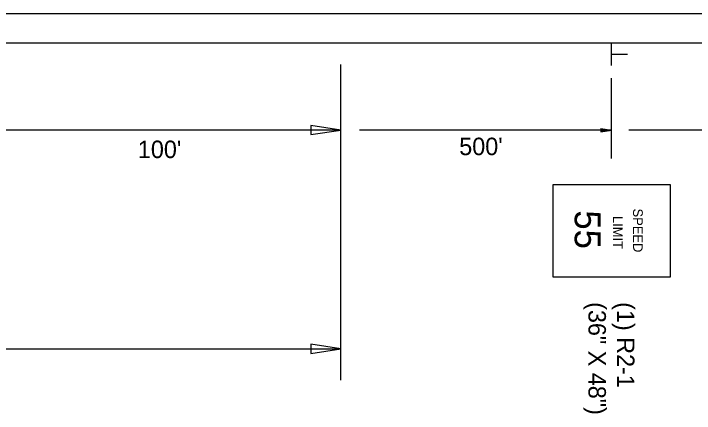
# Model space of a CAD drawing. Extents: x 1678017 to 1687792, y 404433 to 413488.
# Drawn here: x 1678979.75 to 1679003.11, y 409241.21 to 409254.94 of the extents above; entities that cross this region are included whole.
import ezdxf

# ---------------------------------------------------------------- set-up
doc = ezdxf.new("R2010")
doc.units = 0
doc.layers.add('Default', color=7, linetype='Continuous')

msp = doc.modelspace()

# ---------------------------------------------------------------- linework, layer by layer
at = {"layer": 'Default'}
for p, q in [((1678966.108, 409254.939), (1678990.693, 409254.939)), ((1678990.693, 409254.939), (1678997.456, 409254.939)), ((1678997.456, 409254.939), (1679009.188, 409254.939)), ((1678953.639, 409253.939), (1679044.491, 409253.939)), ((1679000.269, 409253.157), (1679000.269, 409253.939)), ((1679000.281, 409253.546), (1679000.815, 409253.546)), ((1678990.975, 409242.349), (1678990.975, 409253.195)), ((1679000.269, 409249.96), (1679000.269, 409252.722)), ((1678990.975, 409250.939), (1678978.514, 409250.939)), ((1678990.977, 409250.939), (1678989.947, 409251.094)), ((1678989.947, 409251.094), (1678989.947, 409250.785)), ((1678989.947, 409250.785), (1678990.977, 409250.939)), ((1679000.269, 409250.939), (1678991.614, 409250.939)), ((1678999.894, 409250.996), (1679000.269, 409250.939)), ((1678999.894, 409250.996), (1678999.894, 409250.883)), ((1678999.894, 409250.986), (1679000.207, 409250.939)), ((1678999.894, 409250.977), (1679000.142, 409250.939)), ((1678999.894, 409250.967), (1679000.08, 409250.939)), ((1678999.894, 409250.958), (1679000.016, 409250.939)), ((1678999.894, 409250.948), (1678999.954, 409250.939)), ((1678999.894, 409250.883), (1679000.269, 409250.939)), ((1678999.894, 409250.921), (1679000.016, 409250.939)), ((1678999.894, 409250.902), (1679000.142, 409250.939)), ((1678999.894, 409250.892), (1679000.207, 409250.939)), ((1678999.894, 409250.911), (1679000.08, 409250.939)), ((1678999.894, 409250.931), (1678999.954, 409250.939)), ((1679009.935, 409250.939), (1679000.861, 409250.939)), ((1678938.639, 409243.428), (1678990.975, 409243.428)), ((1678990.975, 409243.428), (1678989.945, 409243.583)), ((1678989.945, 409243.583), (1678989.945, 409243.273)), ((1678989.945, 409243.273), (1678990.975, 409243.428))]:
    msp.add_line(p, q, dxfattribs=at)
msp.add_lwpolyline([(1679002.278, 409245.887), (1678998.261, 409245.887), (1678998.261, 409249.074), (1679002.278, 409249.074)], close=True, dxfattribs=at)

# ---------------------------------------------------------------- texts
for s, p in [("500'", (1678995.039, 409250.079)), ("100'", (1678984.012, 409249.978))]:
    msp.add_text(s, height=0.6, dxfattribs=at).set_placement(p)
for s, height, p in [('55', 0.8897, (1678999.001, 409248.183)), ('SPEED', 0.332, (1679001.004, 409248.245)), ('LIMIT', 0.332, (1679000.318, 409247.99)), ('(36" X 48")', 0.6, (1678999.473, 409245.031)), ('(1) R2-1', 0.6, (1679000.451, 409245.031))]:
    msp.add_text(s, height=height, rotation=270, dxfattribs=at).set_placement(p)

doc.saveas('drawing.dxf')
